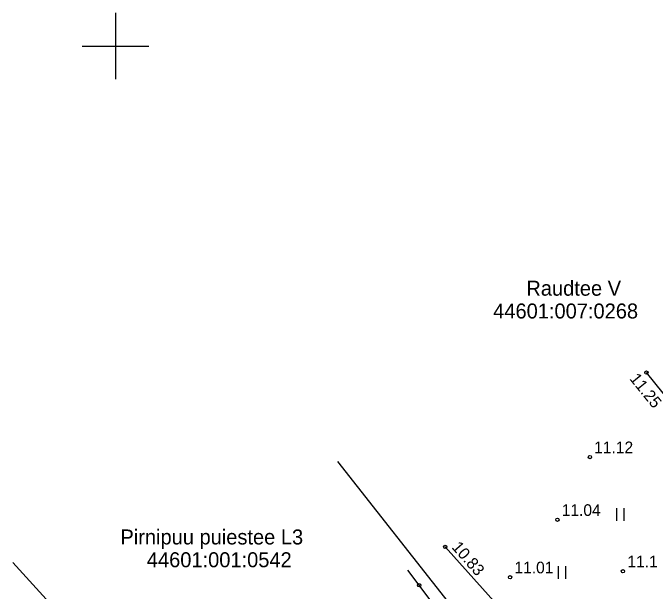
# Model space of a CAD drawing. Extents: x 554198 to 554371, y 6593448 to 6593563.
# Drawn here: x 554243.82 to 554282.11, y 6593517.24 to 6593552 of the extents above; entities that cross this region are included whole.
import ezdxf

# ---------------------------------------------------------------- set-up
doc = ezdxf.new("R2010")
doc.units = 0
for name, color, linetype in [('HALJASTUS', 7, 'Continuous'), ('KORGUS-EH2000', 7, 'Continuous'), ('KTRASS', 7, 'Continuous'), ('PIIR', 7, 'Continuous'), ('RELJEEF', 7, 'Continuous'), ('VEEKOGU', 7, 'Continuous'), ('VORK', 7, 'Continuous')]:
    doc.layers.add(name, color=color, linetype=linetype)

msp = doc.modelspace()

# ---------------------------------------------------------------- linework, layer by layer
at = {"layer": 'HALJASTUS'}
for p, q in [((554280.072, 6593522.238), (554280.072, 6593521.476)), ((554280.528, 6593522.238), (554280.528, 6593521.476)), ((554276.572, 6593518.738), (554276.572, 6593517.976)), ((554277.028, 6593518.738), (554277.028, 6593517.976))]:
    msp.add_line(p, q, dxfattribs=at)
at = {"layer": 'KORGUS-EH2000'}
for centre in [(554281.881, 6593530.377), (554278.48, 6593525.3), (554276.53, 6593521.53), (554269.8, 6593519.901), (554280.47, 6593518.44), (554273.69, 6593518.08), (554268.23, 6593517.601)]:
    msp.add_circle(centre, 0.1, dxfattribs=at)
at = {"layer": 'KTRASS'}
msp.add_lwpolyline([(554243.824, 6593518.956), (554255.375, 6593506.25)], dxfattribs=at)
at = {"layer": 'PIIR'}
msp.add_line((554294.582, 6593485.373), (554263.353, 6593525.033), dxfattribs=at)
at = {"layer": 'RELJEEF'}
msp.add_lwpolyline([(554292.718, 6593514.636), (554292.491, 6593515.065), (554290.64, 6593518.13), (554288.22, 6593521.96), (554286.802, 6593524.059), (554284.31, 6593527.37), (554281.881, 6593530.377)], dxfattribs=at)
at = {"layer": 'VEEKOGU'}
for points in [[(554280.554, 6593507.491), (554280.518, 6593507.828), (554276.294, 6593512.505), (554273.76, 6593515.47), (554269.8, 6593519.901)], [(554289.699, 6593489.692), (554285.677, 6593494.745), (554279.884, 6593502.023), (554278.226, 6593503.871), (554276.897, 6593505.887), (554273.851, 6593510.088), (554268.23, 6593517.601), (554267.552, 6593518.507)]]:
    msp.add_lwpolyline(points, dxfattribs=at)
at = {"layer": 'VORK'}
for p, q in [((554250, 6593552), (554250, 6593548)), ((554248, 6593550), (554252, 6593550))]:
    msp.add_line(p, q, dxfattribs=at)

# ---------------------------------------------------------------- texts
at = {"layer": 'KORGUS-EH2000'}
for s, rotation, p in [(' 11.25 ', 308.9306, (554280.671, 6593530.197)), (' 10.83 ', 311.2845, (554269.975, 6593520.055))]:
    msp.add_text(s, height=0.7, rotation=rotation, dxfattribs=at).set_placement(p)
for s, p in [(' 11.12 ', (554278.48, 6593525.533)), (' 11.04 ', (554276.53, 6593521.763)), (' 11.19 ', (554280.47, 6593518.673)), (' 11.01 ', (554273.69, 6593518.313))]:
    msp.add_text(s, height=0.7, dxfattribs=at).set_placement(p)
at = {"layer": 'PIIR'}
for s, p in [('Raudtee V', (554274.668, 6593534.995)), ('44601:007:0268', (554272.676, 6593533.627)), ('Pirnipuu puiestee L3', (554250.29, 6593520.048)), ('44601:001:0542', (554251.876, 6593518.68))]:
    msp.add_text(s, height=0.9, dxfattribs=at).set_placement(p)

doc.saveas('drawing.dxf')
